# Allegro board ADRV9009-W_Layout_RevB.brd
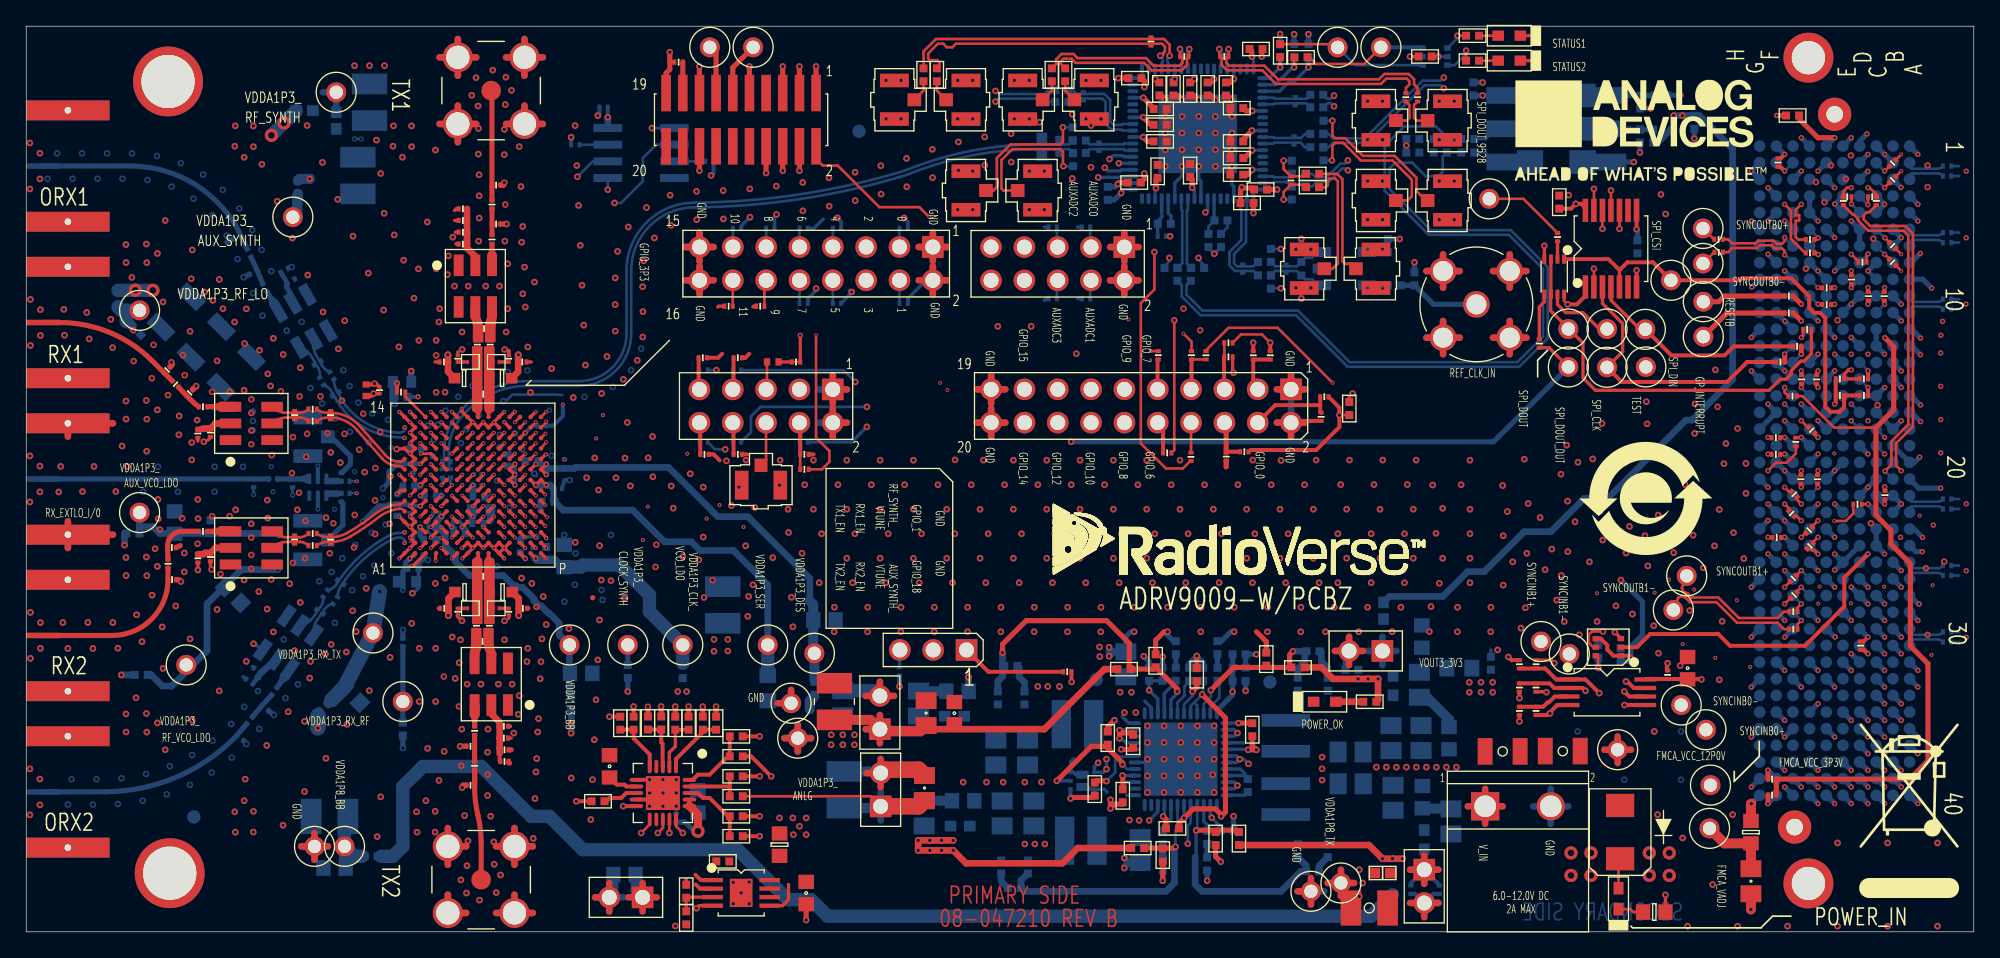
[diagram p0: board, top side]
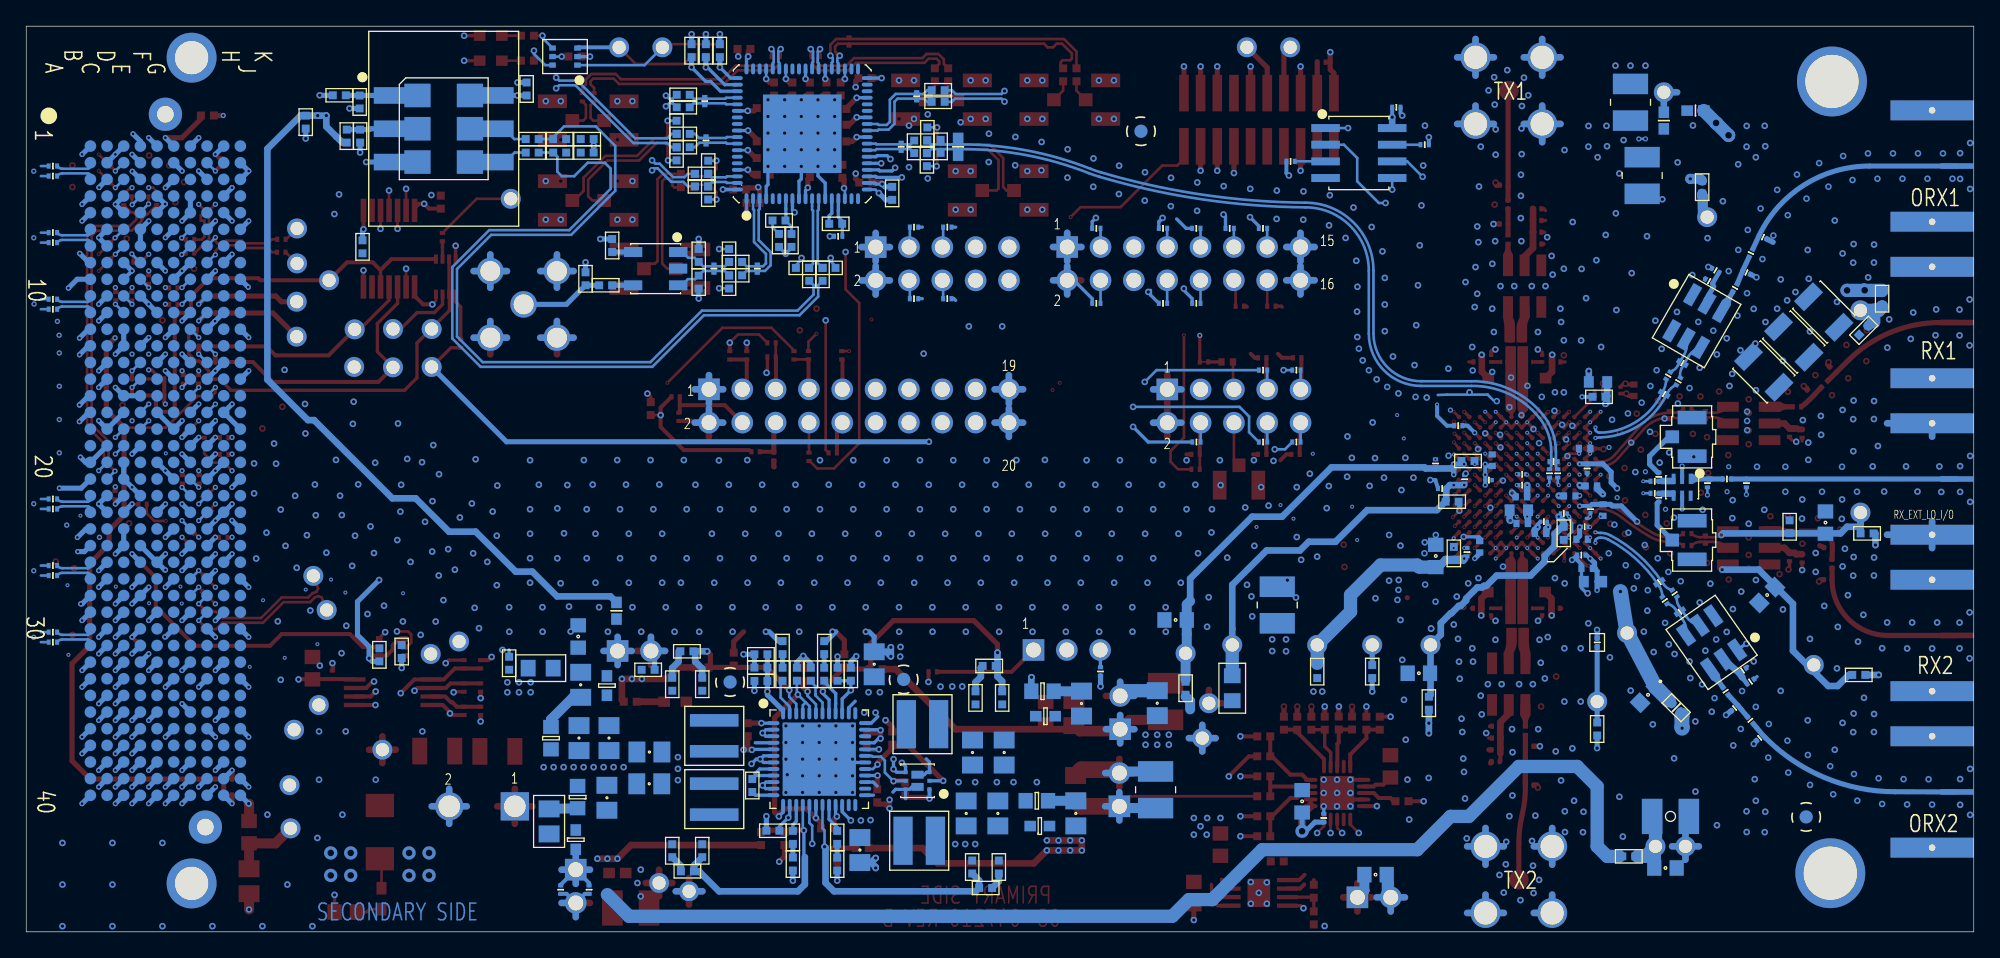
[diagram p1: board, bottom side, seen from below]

Outline 148.44 x 69.09 mm; copper layers: TOP, L2_GND, L3_PWR, L4_GND, L5_SIG, L6_GND, L7_SIG, L8_SIG, L9_GND, L10_SIG, L11_GND, L12_PWR, L13_GND, BOTTOM. Coordinates in mm from the lower left corner of the outline.
Outline path: 0,69.09 0,0 148.44,0 148.44,69.09 0,69.09

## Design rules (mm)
constraint set DEFAULT: min track width 0.203
net group DIFFPAIR0: nets SERDOUT0+ SERDOUT0-
net group DIFFPAIR1: nets SERDOUT1+ SERDOUT1-
net group DIFFPAIR2: nets SERDOUT3+ SERDOUT3-
net group DIFFPAIR3: nets SERDIN3+ SERDIN3-
net group DIFFPAIR4: nets SERDIN0+ SERDIN0-
net group DIFFPAIR5: nets SERDIN2+ SERDIN2-
net group DIFFPAIR13: nets SERDOUT2+ SERDOUT2-
net group DIFFPAIR15: nets SERDIN1+ SERDIN1-
net group DIFFPAIR26: nets GPIO_16 GPIO_17
net group DIFFPAIR27: nets GPIO_13 GPIO_14
net group DIFFPAIR28: nets GPIO_11 GPIO_12
net group DIFFPAIR29: nets GPIO_9 GPIO_10
net group DIFFPAIR30: nets GPIO_8 GPIO_15
net group DIFFPAIR36: nets SYNCOUTB0+ SYNCOUTB0-
net group DIFFPAIR37: nets SYNCINB0+ SYNCINB0-
net group DIFFPAIR38: nets SYNCINB1+ SYNCINB1-
net group DIFFPAIR56: nets SYSREF_IN+ SYSREF_IN-
net group DIFFPAIR59: nets CLK+ CLK-
net group DIFFPAIR63: nets FPGA_SYSREF+ FPGA_SYSREF-
net group DIFFPAIR72: nets VCXO_IN+ VCXO_IN-
net group DIFFPAIR74: nets FPGA_REF_CLK+ FPGA_REF_CLK-
net group DIFFPAIR75: nets DIR_CLK+ DIR_CLK-
net group DIFFPAIR76: nets UNNAMED_2_CAP_I91_N2 UNNAMED_2_CAP_I92_N2
net group DIFFPAIR77: nets UNNAMED_2_CAP_I93_N2 UNNAMED_2_CAP_I94_N2
net group DIFFPAIR78: nets UNNAMED_2_CAP_I95_N2 UNNAMED_2_CAP_I98_N2
net group DIFFPAIR79: nets UNNAMED_2_CAP_I99_N2 UNNAMED_2_CAP_I100_N2
net group DIFFPAIR80: nets UNNAMED_2_CAP_I105_N2 UNNAMED_2_CAP_I106_N2
net group DIFFPAIR81: nets UNNAMED_2_CAP_I101_N2 UNNAMED_2_CAP_I103_N2
net group DIFFPAIR82: nets UNNAMED_2_CAP_I96_N2 UNNAMED_2_CAP_I97_N2
net group DIFFPAIR83: nets UNNAMED_2_CAP_I102_N2 UNNAMED_2_CAP_I104_N2
net group DIFFPAIR84: nets UNNAMED_7_CN400PAK_I55_N15 UNNAMED_7_CN400PAK_I55_N16
net group DIFFPAIR85: nets UNNAMED_7_CN400PAK_I55_N21 UNNAMED_7_CN400PAK_I55_N22
net group DIFFPAIR86: nets UNNAMED_7_CN400PAK_I52_N22 UNNAMED_7_CN400PAK_I52_N23
net group DIFFPAIR87: nets UNNAMED_7_CN400PAK_I55_N24 UNNAMED_7_CN400PAK_I55_N25
net group DIFFPAIR88: nets UNNAMED_4_CAP_I184_N1 UNNAMED_4_RES_I165_N2
net group DIFFPAIR89: nets OUT3 OUT3_N
net group DIFFPAIR91: nets OUT1 OUT1_N
net group DIFFPAIR92: nets UNNAMED_4_CAP_I166_N1 UNNAMED_4_CAP_I177_N1
net group DIFFPAIR93: nets OUT13 OUT13_N
net group DIFFPAIR94: nets OUT12 OUT12_N
net group DIFFPAIR95: nets UNNAMED_7_CN400PAK_I52_N7 UNNAMED_7_CN400PAK_I52_N8
net group DIFFPAIR96: nets UNNAMED_7_CAP_I157_N2 UNNAMED_7_CAP_I158_N2
net group DIFFPAIR97: nets SYNCOUTB1+ SYNCOUTB1-
net group DIFFPAIR98: nets SYSREF_CLK_IN+ SYSREF_CLK_IN-
net group DIFFPAIR99: nets FPGA_SYSREF_OUT+ FPGA_SYSREF_OUT-
net group DIFFPAIR100: nets UNNAMED_4_CNBNC3P_I324_CNTR UNNAMED_4_CNBNC3P_I325_CNTR
net group DIFFPAIR101: nets UNNAMED_4_CAP_I329_N1 UNNAMED_4_CAP_I330_N1
net group DIFFPAIR102: nets REF_CLK_IN+ REF_CLK_IN-
net group DIFFPAIR103: nets ORX1_IN+ ORX1_IN-
net group DIFFPAIR104: nets ORX1_BAL+ ORX1_BAL-
net group DIFFPAIR105: nets RX1_IN+ RX1_IN-
net group DIFFPAIR106: nets RX1_BAL+ RX1_BAL-
net group DIFFPAIR107: nets RF_EXT_LO+ RF_EXT_LO-
net group DIFFPAIR108: nets UNNAMED_10_CAP_I10_N1 UNNAMED_10_CAP_I11_N1
net group DIFFPAIR109: nets RX2_IN+ RX2_IN-
net group DIFFPAIR110: nets RX2_BAL+ RX2_BAL-
net group DIFFPAIR111: nets ORX2_IN+ ORX2_IN-
net group DIFFPAIR112: nets ORX2_BAL+ ORX2_BAL-
net group DIFFPAIR113: nets UNNAMED_4_CNBNC3P_I318_CNTR UNNAMED_4_CNBNC3P_I321_CNTR
net group DIFFPAIR114: nets UNNAMED_4_CAP_I292_N2 UNNAMED_4_CAP_I294_N2
net group DIFFPAIR115: nets OUT5 OUT5_N
net group DIFFPAIR116: nets UNNAMED_4_CAP_I303_N2 UNNAMED_4_CAP_I304_N2
net group DIFFPAIR117: nets OUT7 OUT7_N
net group DIFFPAIR118: nets UNNAMED_4_CNBNC3P_I306_CNTR UNNAMED_4_CNBNC3P_I308_CNTR
net group DIFFPAIR119: nets OUT8 OUT8_N
net group DIFFPAIR120: nets UNNAMED_4_CNBNC3P_I148_CNTR UNNAMED_4_CNBNC3P_I248_CNTR
nets with their own width: min track width 0.254; nets AGND

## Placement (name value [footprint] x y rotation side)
C6  0.1uF  [C0402]  111.64 20.49 270 bottom
C101  1uF  [C0402#2]  37.66 29.38 90 bottom
C102  1uF  [C0402#2]  30.8 33.25 0 bottom
C103  0.1uF  [C0201]  32.34 34.97 270 bottom
C104  0.1uF  [C0201]  31.71 34.97 270 bottom
C105  0.1uF  [C0201]  146.41 58.42 0 bottom
C106  0.1uF  [C0201]  146.41 57.66 0 bottom
C107  0.1uF  [C0201]  146.41 53.34 0 bottom
C108  0.1uF  [C0201]  146.41 52.58 0 bottom
C109  0.1uF  [C0201]  142.25 52.35 315 top
C110  0.1uF  [C0201]  142.25 51.08 315 top
C111  0.1uF  [C0201]  146.41 48.26 0 bottom
C112  0.1uF  [C0201]  146.41 47.5 0 bottom
C113  0.1uF  [C0201]  146.41 33.02 0 bottom
C114  0.1uF  [C0201]  146.41 32.26 0 bottom
C115  0.1uF  [C0201]  146.41 22.86 0 bottom
C116  0.1uF  [C0201]  146.41 22.1 0 bottom
C117  0.1uF  [C0201]  142.25 58.64 45 top
C118  0.1uF  [C0201]  142.25 57.37 45 top
C119  0.1uF  [C0201]  146.41 27.94 0 bottom
C120  0.1uF  [C0201]  146.41 27.18 0 bottom
C121  0.1uF  [C0201]  66.87 53.67 0 bottom
C122  0.1uF  [C0201]  66.87 47.95 0 bottom
C123  0.1uF  [C0201]  61.79 53.67 0 bottom
C124  0.1uF  [C0201]  61.79 47.95 0 bottom
C125  0.1uF  [C0201]  59.25 53.67 0 bottom
C126  0.1uF  [C0201]  59.25 47.95 0 bottom
C127  0.1uF  [C0201]  56.71 53.67 0 bottom
C128  0.1uF  [C0201]  55.95 47.73 180 top
C129  0.1uF  [C0201]  54.17 53.67 0 bottom
C130  0.1uF  [C0201]  53.53 47.73 180 top
C131  0.1uF  [C0201]  80.77 53.76 180 bottom
C132  0.1uF  [C0201]  80.77 48.3 180 bottom
C133  0.1uF  [C0201]  78.23 53.76 180 bottom
C134  0.1uF  [C0201]  78.23 48.3 180 bottom
C135  0.1uF  [C0201]  44.01 62.9 180 bottom
C136  1uF  [C0402#2]  56.9 43.47 0 top
C137  1uF  [C0402#2]  29.66 36.87 180 bottom
C201  TBD0201  [C0201]  10.74 42.87 45 top
C203  TBD0201  [C0201]  12.45 41.12 45 top
C204  TBD0201  [C0201]  20.46 39.42 90 top
C207  TBD0201  [C0201]  23.2 39.42 90 top
C208  TBD0201  [C0201]  11.12 26.87 0 top
C210  TBD0201  [C0201]  11.09 29.31 0 top
C211  TBD0201  [C0201]  20.46 29.92 90 top
C214  TBD0201  [C0201]  23.2 29.92 90 top
C215  TBD0201  [C0201]  16.07 52.99 205 bottom
C217  TBD0201  [C0201]  17.32 50.3 205 bottom
C218  TBD0201  [C0201]  22.21 43.39 210 bottom
C221  TBD0201  [C0201]  23.6 41.04 210 bottom
C222  TBD0201  [C0201]  16.31 14.79 320 bottom
C224  TBD0201  [C0201]  18.22 17.07 320 bottom
C225  TBD0201  [C0201]  22.39 24.42 325 bottom
C228  TBD0201  [C0201]  23.97 26.67 325 bottom
C240  10pF  [C0201]  13.08 38.01 90 top
C241  27PF  [C0201]  14.04 38.08 90 top
C242  82PF  [C0201]  14.04 28.59 90 top
C243  27PF  [C0201]  13.08 28.49 270 top
C244  10pF  [C0201]  19.69 50.46 30 bottom
C245  27PF  [C0201]  20.17 49.64 210 bottom
C246  10pF  [C0201]  17.02 19.09 145 bottom
C247  27PF  [C0201]  17.62 19.93 325 bottom
C248  18PF  [C0201]  13.47 40.05 0 top
C249  18PF  [C0201]  13.47 30.56 0 top
C250  18PF  [C0201]  18.2 49.13 300 bottom
C251  18PF  [C0201]  18.91 18.36 55 bottom
C301  TBD0201  [C0201]  17.33 34.23 270 bottom
C303  TBD0201  [C0201]  20.3 34.23 270 bottom
C304  100pF  [C0201]  24.32 34.37 0 bottom
C305  100pF  [C0201]  24.32 33.45 0 bottom
C307  0.1uF  [C0201]  31.83 43.47 180 top
C308  0.1uF  [C0201]  37.81 43.47 0 top
C312  TBD0201  [C0201]  35.82 54 0 top
C314  TBD0201  [C0201]  35.82 56.97 0 top
C315  0.1uF  [C0201]  37.85 24.68 0 top
C316  0.1uF  [C0201]  31.87 24.68 180 top
C320  TBD0201  [C0201]  33.86 14.15 180 top
C322  TBD0201  [C0201]  33.86 11.18 180 top
C323  TBD0201  [C0201]  32.9 43.73 90 top
C325  TBD0201  [C0201]  36.78 43.73 90 top
C327  TBD0201  [C0201]  36.78 24.42 270 top
C329  TBD0201  [C0201]  32.9 24.42 270 top
C336  18PF  [C0201]  34.18 15.34 270 top
C337  18PF  [C0201]  35.5 52.82 90 top
C338  TBD0201  [C0201]  34.9 46.01 0 top
C339  TBD0201  [C0201]  34.84 41.03 0 top
C341  TBD0201  [C0201]  34.84 27.12 180 top
C342  TBD0201  [C0201]  34.77 22.15 180 top
C344  51PF  [C0201]  33.28 54.27 0 top
C345  75PF  [C0201]  33.28 55.16 0 top
C346  10pF  [C0201]  33.28 52.47 0 top
C347  27PF  [C0201]  33.28 53.37 0 top
C348  10pF  [C0201]  36.4 15.68 180 top
C349  27PF  [C0201]  36.4 14.78 180 top
C350  51PF  [C0201]  36.45 13.88 180 top
C351  75PF  [C0201]  36.45 12.99 180 top
C401  0.1uF  [C0402]  104.28 49.32 180 bottom
C402  0.1uF  [C0402]  94.87 51.6 90 bottom
C403  0.1uF  [C0402]  94.37 51.1 180 bottom
C404  0.1uF  [C0402]  94.87 49.57 270 bottom
C405  0.1uF  [C0402]  94.37 50.09 180 bottom
C406  0.33uF  [C0402]  123.02 63.31 270 bottom
C407  0.1uF  [C0402]  110.3 64.3 270 bottom
C408  0.1uF  [C0402]  105.68 59.45 180 bottom
C409  0.1uF  [C0402]  88.76 50.16 90 bottom
C410  100pF  [C0201]  105.16 63.67 270 top
C411  100pF  [C0201]  106.05 63.67 270 top
C412  0.01uF  [C0402]  78.17 65.38 270 top
C413  0.01uF  [C0402]  79.19 65.38 270 top
C414  180pF  [C0402]  90.11 52.74 90 bottom
C415  1uF  [C0402]  91.06 52.74 90 bottom
C416  1000pF  [C0402]  86.74 54.01 0 bottom
C417  0.47uF  [C0201]  86.55 53.06 0 bottom
C418  0.1uF  [C0402]  86.43 60.3 0 top
C419  0.1uF  [C0402]  96.46 58.33 270 bottom
C420  0.1uF  [C0402]  96.46 56.36 90 bottom
C421  0.1uF  [C0402]  121.52 21.13 270 bottom
C422  0.1uF  [C0402]  119.82 21.38 270 bottom
C423  0.1uF  [C0402]  122.81 52.26 90 bottom
C424  0.1uF  [C0402]  116.84 55.67 270 top
C425  0.1uF  [C0402]  100.84 39.92 90 top
C426  1uF  [C0402]  86.24 58.02 90 top
C427  0.1uF  [C0402]  88.71 58.08 270 top
C428  0.1uF  [C0402]  93.04 55.6 0 top
C429  0.1uF  [C0402]  94.08 56.63 0 top
C430  0.1uF  [C0402]  92.27 57.76 0 top
C431  0.1uF  [C0402]  92.27 59.03 0 top
C432  0.1uF  [C0402]  92.27 60.3 0 top
C433  0.1uF  [C0402]  92.27 62.84 0 top
C434  0.1uF  [C0402]  93.73 67.35 180 top
C435  0.1uF  [C0402]  91.44 64.3 90 top
C436  0.1uF  [C0402]  90.05 64.3 90 top
C437  0.1uF  [C0402]  88.71 64.3 90 top
C438  0.1uF  [C0402]  87.44 64.3 90 top
C439  0.1uF  [C0402]  86.36 64.3 90 top
C440  0.1uF  [C0402]  106.62 66.78 0 top
C441  0.1uF  [C0402]  84.45 57.16 180 top
C442  0.1uF  [C0402]  86.43 61.57 180 top
C443  0.1uF  [C0402]  86.43 62.78 180 top
C444  0.1uF  [C0402]  84.51 65.13 180 top
C445  TBD0402  [C0402]  78.74 59.92 270 bottom
C601  10uF  [C0603]  70.74 16.68 90 top
C602  220UF  [C1210-2]  61.6 17.57 90 top
C603  10uF  [C0603]  42.29 19.72 0 bottom
C604  0.1uF  [C0201]  31.24 31.92 180 bottom
C605  1uF  [C0402]  31.25 30.4 270 bottom
C606  220UF  [C1210-2]  25.28 57.7 270 bottom
C607  220UF  [C1210-2]  26.16 63.29 90 bottom
C608  0.1uF  [C0201]  34.42 34.08 0 bottom
C609  1uF  [C0402#2]  34.48 33.19 0 bottom
C610  10uF  [C0603]  41 28.67 90 bottom
C611  0.1uF  [C0201]  38.63 28.96 90 bottom
C612  1uF  [C0402]  39.63 28.87 90 bottom
C613  10uF  [C0603#2]  29.02 26.71 0 bottom
C614  1uF  [C0402#2]  29.47 27.73 0 bottom
C615  0.1uF  [C0201]  29.91 28.74 0 bottom
C616  10uF  [C0603#2]  34.67 32.17 0 bottom
C617  1uF  [C0402#2]  34.42 31.15 0 bottom
C618  10uF  [C0603]  24.83 18.08 315 bottom
C619  0.1uF  [C0201]  29.66 30.9 180 bottom
C620  1uF  [C0402#2]  29.85 29.95 180 bottom
C621  10uF  [C0603]  11.31 31.22 90 bottom
C622  0.1uF  [C0201]  29.47 35.35 270 bottom
C623  1uF  [C0402]  14.04 30.9 90 bottom
C624  220UF  [C1210-2#2]  13.72 45 45 bottom
C625  220UF  [C1210-2#2]  11.43 47.28 45 bottom
C626  220UF  [C1210-2#2]  16 42.71 45 bottom
C627  1uF  [C0402#2]  29.15 34.01 180 bottom
C628  10uF  [C0603]  15.75 25.69 315 bottom
C629  0.1uF  [C0201]  29.21 32.23 270 bottom
C630  1uF  [C0402#2]  28.26 32.17 270 bottom
C631  10uF  [C0603#2]  28.64 41.95 0 bottom
C632  0.1uF  [C0201]  34.42 34.9 0 bottom
C633  1uF  [C0402]  28.56 40.81 0 bottom
C634  0.1uF  [C0201]  40.52 33.82 0 bottom
C635  1uF  [C0402]  39.76 32.81 180 bottom
C636  0.1uF  [C0201]  38.8 34.52 90 bottom
C637  10uF  [C0603]  60.84 23.79 0 bottom
C638  0.1uF  [C0201]  41.02 35.73 90 bottom
C639  1uF  [C0402]  38.55 35.92 180 bottom
C640  220UF  [C1210-2]  62.36 10.83 90 bottom
C641  220UF  [C1210-2]  53.09 24.93 90 bottom
C642  0.1uF  [C0201]  36.96 34.46 180 bottom
C643  1uF  [C0402#2]  36.71 35.98 90 bottom
C701  0.1uF  [C0201]  49.54 8.68 270 bottom
C702  10uF  [C0603]  51.19 9.95 90 bottom
C703  10uF  [C0603]  126.63 20.11 90 top
C704  0.1uF  [C0201]  125.1 19.6 90 top
C705  10uF  [C0603]  44.46 12.62 90 top
C706  1uF  [C0402]  43.58 9.96 180 top
C801  0.01uF  [C0201]  140.7 56.06 180 top
C802  0.01uF  [C0201]  138.8 56.06 0 top
C803  0.01uF  [C0201]  141.01 55.76 270 top
C804  0.01uF  [C0201]  138.5 55.76 270 top
C901  10uF  [C0805H60]  83.81 20.41 90 bottom
C902  1uF  [C0402]  89.7 19.65 270 bottom
C903  1uF  [C0402]  89.22 19.62 270 top
C904  0.0027uF  [C0402]  87.62 21.68 270 bottom
C905  10uF  [C0805H60]  84.9 6.24 270 bottom
C906  0.0027uF  [C0402]  86.63 5.17 90 bottom
C907  10uF  [C0805H60]  100.94 13.72 0 bottom
C908  0.0033uF  [C0402]  90.79 21.68 270 bottom
C909  10uF  [C0805H60]  100.95 11.29 0 bottom
C910  0.0033uF  [C0402]  90 5.17 90 bottom
C911  TBD0402  [C0402]  86.6 19.65 270 bottom
C912  TBD0402  [C0402]  92.44 21.17 180 bottom
C913  0.1uF  [C0402]  84.37 14.54 90 top
C914  0.01uF  [C0402]  76.09 17.84 270 bottom
C915  0.1uF  [C0402]  83.58 10.38 90 top
C916  0.01uF  [C0402]  74.31 4.94 90 bottom
C917  0.1uF  [C0402]  93.45 15.42 270 top
C918  0.01uF  [C0402]  99.2 18.88 270 bottom
C919  0.1uF  [C0402]  93.1 11.16 90 bottom
C920  0.01uF  [C0402]  99.2 6.18 90 bottom
C921  47uF  [C0805H60]  76.31 13.68 270 bottom
C922  47uF  [C0805H60]  73.9 13.68 270 bottom
C924  47uF  [C0805H60]  68.01 17.41 90 bottom
C925  47uF  [C0805H60]  76.8 9.03 90 bottom
C926  47uF  [C0805H60]  74.38 9.03 90 bottom
C927  47uF  [C0805H60]  68.44 9.03 90 bottom
C928  47uF  [C0805H60]  104.02 14.78 270 bottom
C929  47uF  [C0805H60]  106.18 18.84 270 bottom
C930  47uF  [C0805H60]  104.18 10.22 90 bottom
C931  22uF  [C0805H53]  108.59 8.42 90 bottom
C932  47uF  [C0805H60]  131.45 3.86 270 top
C933  4.7uF  [C0603]  59.45 2.96 90 top
C934  4.7uF  [C0603]  45.6 4.36 0 bottom
C935  0.01uF  [C0402]  53.09 5.37 180 top
C936  10uF  [C0603]  106.37 22.53 90 bottom
C937  0.01uF  [C0402]  101.04 19.99 0 bottom
C938  0.1uF  [C0402]  127.14 61.77 90 bottom
C939  47uF  [C0805H60]  106.31 14.78 270 bottom
C940  0.1uF  [C0201]  105.54 3.21 90 bottom
C941  0.01uF  [C0201]  107.7 3.21 90 bottom
C942  100uF  [C1210]  23.12 8.8 180 bottom
C943  10uF  [C0603]  23.5 4.87 180 bottom
C944  0.1uF  [C0201]  32.77 31.28 0 bottom
C945  1uF  [C0402#2]  33.02 30.39 0 bottom
C946  100uF  [C1210]  102.36 1.82 0 top
C947  0.1uF  [C0201]  26.93 41.31 90 top
C948  1uF  [C0402#2]  25.91 41.31 90 top
C949  47uF  [C0805H60]  62.23 17.44 90 bottom
C950  47uF  [C0805H60]  68.59 16.68 90 top
C951  47uF  [C0805H60]  68.46 10.97 90 top
CR901  S2A-LT  [DO214AA3]  121.48 7.6 90 top
DS401  LNJ326W83RA  [LED0603_A]  113.03 66.46 180 top
DS402  LNJ326W83RA  [LED0603_A]  113.03 68.37 180 top
DS901  LNJ926W8CRA  [LED0603]  121.36 2.52 90 top
DS902  LNJ326W83RA  [LED0603_A]  98.97 17.55 0 top
E602  1.8K OHM AT 100MEGHZ  [L0402]  21.21 62.65 0 bottom
E611  42OHM AT 100MEGHZ  [L0805]  56.52 18.58 90 bottom
E613  1.8KOHM AT 100MEGHZ  [L0402]  23.62 61.89 270 bottom
E901  120OHM  [L0603]  70.75 16.45 180 bottom
E902  470OHM  [L0603]  71.18 8.06 180 bottom
E903  470OHM  [L0603]  104.18 18.78 90 bottom
E904  470OHM  [L0603]  106.56 7.02 270 bottom
E905  42OHM AT 100MEGHZ  [L0805]  109.23 20.11 0 bottom
E906  30OHM  [L0402]  103.45 24.49 90 bottom
E907  30OHM  [L0402]  103.38 4.48 180 top
F901  2A  [F1206]  117.11 13.78 180 top
F902  2A  [F1206]  112.53 13.76 0 top
J101  U.FL-R-SMT-1(01)  [CNHIROSE-U_FL-R-SMT-1]  56 34.07 180 top
J201  132255-11  [CNAMPHENOL132255-11]  0.76 46.48 180 top
J202  132255-11  [CNAMPHENOL132255-11]  0.76 22.61 180 top
J203  132255-11  [CNAMPHENOL132255-11]  0.76 58.42 180 bottom
J204  132255-11  [CNAMPHENOL132255-11]  0.76 10.67 180 bottom
J301  132255-11  [CNAMPHENOL132255-11]  0.76 34.54 180 bottom
J303  132134-15  [CNSMSMASQ276H379]  35.44 64.17 90 top
J304  132134-15  [CNSMSMASQ276H379]  34.67 3.98 90 top
J305  U.FL-R-SMT-1(01)  [CNHIROSE-U_FL-R-SMT-1]  21.47 37.76 270 bottom
J306  U.FL-R-SMT-1(01)  [CNHIROSE-U_FL-R-SMT-1]  21.47 29.88 270 bottom
J401  142-0701-201  [CNJOHNSON142-0701-201]  110.53 47.87 0 top
J402  U.FL-R-SMT-1(01)  [CNHIROSE-U_FL-R-SMT-1]  102.87 55.79 90 top
J403  U.FL-R-SMT-1(01)  [CNHIROSE-U_FL-R-SMT-1]  108.33 55.79 270 top
J404  U.FL-R-SMT-1(01)  [CNHIROSE-U_FL-R-SMT-1]  102.87 61.89 90 top
J405  U.FL-R-SMT-1(01)  [CNHIROSE-U_FL-R-SMT-1]  108.33 61.89 270 top
J406  U.FL-R-SMT-1(01)  [CNHIROSE-U_FL-R-SMT-1]  75.95 63.48 90 top
J407  U.FL-R-SMT-1(01)  [CNHIROSE-U_FL-R-SMT-1]  81.41 63.48 270 top
J408  U.FL-R-SMT-1(01)  [CNHIROSE-U_FL-R-SMT-1]  71.63 63.48 270 top
J409  U.FL-R-SMT-1(01)  [CNHIROSE-U_FL-R-SMT-1]  66.17 63.48 90 top
J410  U.FL-R-SMT-1(01)  [CNHIROSE-U_FL-R-SMT-1]  71.63 56.55 90 top
J411  U.FL-R-SMT-1(01)  [CNHIROSE-U_FL-R-SMT-1]  77.09 56.55 270 top
J412  U.FL-R-SMT-1(01)  [CNHIROSE-U_FL-R-SMT-1]  102.87 50.59 270 top
J413  U.FL-R-SMT-1(01)  [CNHIROSE-U_FL-R-SMT-1]  97.41 50.59 90 top
L307  43NH  [L0603]  33.37 42.24 180 top
L308  43NH  [L0603]  36.27 42.24 180 top
L315  43NH  [L0603]  36.3 25.92 0 top
L316  43NH  [L0603]  33.41 25.92 0 top
L323  TBD0201  [L0201]  33.85 43.47 180 top
L325  TBD0201  [L0201]  35.82 43.47 0 top
L327  TBD0201  [L0201]  35.82 24.68 0 top
L329  TBD0201  [L0201]  33.85 24.68 180 top
L401  TBD0402  [L0402]  77.41 59.89 90 bottom
L612  TBD0201  [L0201]  28.7 22.07 90 bottom
L900  2.2uH  [LSMSQ157H83]  80.12 15.84 180 bottom
L901  2.2uH  [LSMSQ157H83]  80.38 6.95 180 bottom
L902  6.8uH  [LSMSQ157H122]  96 14.95 90 bottom
L903  6.8uH  [LSMSQ157H122]  96 10.12 270 bottom
NOREF  -  []  -140.27 -283.34 0 top
NOREF#2  -  []  123.07 61.13 0 top
NOREF#3  -  [unnamed#2]  135.84 66.69 0 top
NOREF#4  -  [unnamed#2]  135.84 3.69 0 top
NOREF#5  -  []  -96.05 -19.57 0 top
NOREF#6  -  []  123.45 33.06 0 top
NOREF#7  -  []  250.38 218.8 0 top
NOREF#8  -  []  65.26 90.52 0 top
NOREF#9  -  []  -140.27 -283.34 0 top
NOREF#10  -  [unnamed#2]  10.93 4.47 0 top
NOREF#11  -  [unnamed#2]  10.81 64.87 0 top
NOREF#12  -  []  0 69.09 0 top
NOREF#13  -  []  280.93 -40.72 0 top
NOREF#14  -  []  3.55 -12.7 90 top
NOREF#15  -  []  154.73 137.11 0 top
NOREF#16  -  []  100.91 114.35 0 top
NOREF#17  -  []  -140.27 -283.34 0 top
NOREF#18  -  []  148.44 0 90 top
NOREF#19  -  []  152.78 19.47 0 top
NOREF#20  -  [unnamed#2]  12.78 8.76 0 bottom
NOREF#21  -  [unnamed#2]  63.47 61.07 90 bottom
NOREF#22  -  [unnamed#2]  81.56 19.25 0 bottom
NOREF#23  -  [unnamed#2]  94.79 19.06 0 bottom
P101  TSW-110-08-G-D  [CNBERG2X10H330LD36]  96.4 41.39 180 top
P102  TSW-108-08-G-D  [CNSAMTECTSW-108-08-G-D-ST]  69.1 52.24 180 top
P103  TSW-105-08-G-D  [CNSAMTEC2X5H338LD36]  83.7 52.24 180 top
P104  TSW-105-08-G-D  [CNSAMTEC2X5H338LD36]  61.47 41.38 180 top
P701  FTSH-110-01-L-DV-K  [CNHDR2X10H251]  54.49 61.95 180 top
P801  ASP-134488-01  [CNSAMTECASP-134488-01]  143.55 59.94 270 bottom
P901  Z5.530.3225.0  [CNWIELAND3225]  111.2 9.57 0 top
P902  TSW-103-08-G-S  [CNBERG1X3H205LD36]  71.67 21.5 180 top
P903  TSW-102-08-G-S  [CNSAMTEC1X2H330LD36]  65.06 16.73 90 top
P904  TSW-102-08-G-S  [CNSAMTEC1X2H330LD36]  65.12 10.84 90 top
P905  TSW-102-08-G-S  [CNSAMTEC1X2H330LD36]  102.1 21.42 180 top
P906  TSW-102-08-G-S  [CNSAMTEC1X2H330LD36]  106.56 3.47 270 top
P907  TSW-102-08-G-S  [CNSAMTEC1X2H330LD36]  45.71 2.63 180 top
Q901  SIA906EDJ-T1-GE3  [POWERPAKSC70-6]  80.51 11.52 90 bottom
R101  14.3K  [R0201]  28.57 41.18 180 top
R102  10K  [R0201]  91.63 44.93 180 top
R103  10K  [R0201]  91.63 43.85 0 top
R104  10K  [R0201]  92.85 36.62 180 top
R105  10K  [R0201]  91.46 36.25 270 top
R106  10K  [R0201]  94.81 43.98 270 top
R107  10K  [R0201]  93.52 43.98 90 top
R108  10K  [R0201]  98.94 40.81 180 top
R109  10K  [R0201]  98.69 39.29 270 top
R110  10K  [R0201]  39.29 38.61 0 bottom
R111  10K  [R0201]  133.07 11.65 0 top
R112  1K  [R0201]  133.07 10.43 180 top
R113  10K  [R0201]  59.31 36.43 0 top
R114  10K  [R0201]  51.69 36.43 0 top
R115  10K  [R0201]  51.56 43.79 0 top
R116  10K  [R0201]  54.23 36.43 0 top
R117  10K  [R0201]  54.23 43.79 0 top
R118  10K  [R0201]  58.68 43.47 0 top
R119  10K  [R0201]  41.85 60.05 0 bottom
R120  10K  [R0201]  52.07 58.78 180 bottom
R121  100  [R0201]  32.03 35.86 180 bottom
R202  0  [R0201]  11.38 41.78 315 top
R205  0  [R0201]  21.83 38.96 0 top
R206  0  [R0201]  21.83 39.87 0 top
R209  0  [R0201]  10.8 28.08 90 top
R212  0  [R0201]  21.83 29.47 0 top
R213  0  [R0201]  21.83 30.38 0 top
R216  0  [R0201]  16.98 51.78 295 bottom
R219  0  [R0201]  23.29 42.43 300 bottom
R220  0  [R0201]  22.51 42 300 bottom
R223  0  [R0201]  17.03 16.14 50 bottom
R226  0  [R0201]  22.8 25.81 55 bottom
R227  0  [R0201]  23.55 25.28 55 bottom
R302  0  [R0201]  18.82 34.54 0 bottom
R304  0  [R0201]  24.01 34.71 270 bottom
R305  0  [R0201]  24.01 33.12 90 bottom
R307  0  [R0201]  34.38 44.8 90 top
R308  0  [R0201]  35.36 44.8 90 top
R309  0  [R0201]  35.5 55.48 90 top
R310  0  [R0201]  35.29 23.35 270 top
R311  0  [R0201]  34.32 23.35 270 top
R312  0  [R0201]  34.18 12.67 270 top
R401  49.9  [R0402]  105.81 49.82 270 bottom
R402  0  [R0402]  103.78 52.36 270 bottom
R403  24.9  [R0402]  97.18 51.6 90 bottom
R404  24.9  [R0402]  97.18 49.57 90 bottom
R405  100  [R0201]  96.02 50.59 270 bottom
R406  100  [R0201]  92.72 50.59 270 bottom
R407  0  [R0402]  124.57 63.82 180 bottom
R408  0  [R0402]  124.01 60.71 90 bottom
R409  0  [R0402]  122.99 60.71 90 bottom
R410  0  [R0402]  109.87 59.45 180 bottom
R411  0  [R0402]  87.74 50.16 90 bottom
R412  49.9  [R0402]  107.78 59.45 0 bottom
R413  0  [R0402]  107.78 60.48 180 bottom
R414  0  [R0402]  105.68 60.48 180 bottom
R415  0  [R0402]  87.25 50.65 180 bottom
R416  0  [R0402]  89.28 50.65 0 bottom
R417  0  [R0402]  109.87 60.48 180 bottom
R418  100  [R0201]  96.63 60.37 270 bottom
R419  0  [R0402]  98.36 59.86 0 bottom
R420  0  [R0402]  98.36 60.87 0 bottom
R421  0  [R0402]  98.87 59.35 90 bottom
R422  0  [R0402]  98.87 61.38 270 bottom
R423  100  [R0201]  96.72 63.38 90 bottom
R424  0  [R0402]  98.36 63.86 0 bottom
R425  0  [R0402]  98.36 62.9 0 bottom
R426  100  [R0201]  91.32 66.78 0 top
R427  100  [R0201]  88.27 66.78 0 top
R428  100  [R0201]  85.73 67.92 90 top
R429  0  [R0402]  69.41 65.38 270 top
R430  0  [R0402]  68.39 65.38 270 top
R431  100  [R0201]  80.57 63.74 270 bottom
R432  0  [R0402]  78.93 63.32 180 bottom
R433  0  [R0402]  78.93 64.21 180 bottom
R434  100  [R0201]  81.75 59.89 90 bottom
R435  0  [R0402]  80.27 60.36 180 bottom
R436  0  [R0402]  80.27 59.41 180 bottom
R437  0  [R0402]  79.76 60.87 90 bottom
R438  0  [R0402]  79.79 58.9 270 bottom
R439  10.2K  [R0402]  91.06 54.27 180 bottom
R440  10K  [R0402]  82.44 56.34 270 bottom
R441  10K  [R0402]  97.73 67.22 270 bottom
R442  10K  [R0402]  95.57 67.22 90 bottom
R443  10K  [R0402]  96.64 67.22 90 bottom
R444  0  [R0402]  95.57 67.22 90 top
R445  0  [R0402]  97.16 66.71 0 top
R446  200  [R0402]  110.24 66.46 0 top
R447  200  [R0402]  110.24 68.37 0 top
R448  0  [R0402]  98.05 57.82 180 top
R449  0  [R0402]  98.05 56.81 180 top
R450  100  [R0201]  96.4 57.32 270 top
R451  0  [R0402]  96.97 57.82 180 bottom
R452  0  [R0402]  96.97 56.87 180 bottom
R453  0  [R0201]  116.72 53 90 top
R454  0  [R0201]  115.33 44.88 270 top
R601  0  [R0402]  41.53 17.44 90 bottom
R603  0  [R0402]  50.04 19.85 90 bottom
R604  0  [R0402]  28.7 15.47 90 bottom
R605  0  [R0402]  45.85 19.85 90 bottom
R606  0  [R0402]  22.68 17.1 45 bottom
R607  0  [R0402]  8.13 30.39 0 bottom
R608  0  [R0402]  6.99 48.3 270 bottom
R609  0  [R0402]  8.77 19.6 0 bottom
R610  0  [R0402]  20.7 56.81 270 bottom
R611  0  [R0402]  60.07 18.58 90 bottom
R612  0  [R0201]  28.7 22.07 90 bottom
R613  0.1  [R0402]  8.38 45.89 315 bottom
R701  47K  [R0201]  49.72 66.35 0 top
R702  0  [R0201]  86.28 43.99 270 top
R704  0  [R0201]  59.31 35.28 180 top
R705  0  [R0201]  88.82 43.99 270 top
R706  0  [R0201]  86.97 36.53 180 top
R707  0  [R0201]  88.78 36.23 90 top
R708  20K  [R0201]  113.8 20.41 90 top
R709  20K  [R0201]  113.8 18.63 270 top
R710  20K  [R0201]  113.8 16.85 270 top
R711  20K  [R0201]  115.07 20.41 270 top
R712  20K  [R0201]  115.07 18.63 90 top
R713  20K  [R0201]  115.07 16.85 90 top
R714  56K  [R0402]  54.12 7.29 0 top
R715  10K  [R0402]  54.12 8.81 0 top
R716  10K  [R0402]  54.12 10.34 180 top
R717  10K  [R0402]  54.12 11.86 180 top
R718  10K  [R0402]  54.12 13.39 180 top
R719  10K  [R0402]  54.12 14.91 180 top
R720  10K  [R0402]  51.56 15.91 270 top
R721  10K  [R0402]  52.58 15.91 270 top
R722  10K  [R0402]  49.47 15.91 270 top
R723  10K  [R0402]  50.48 15.91 270 top
R724  10K  [R0402]  47.39 15.93 270 top
R725  10K  [R0402]  48.4 15.93 270 top
R726  10K  [R0402]  45.28 15.91 270 top
R727  10K  [R0402]  46.29 15.91 270 top
R801  0  [R0201]  133.52 58.69 270 top
R802  0  [R0201]  128.99 52.83 0 top
R803  0  [R0201]  129 51.84 0 top
R804  0  [R0201]  134.34 48.5 0 top
R805  0  [R0201]  134.34 47.21 0 top
R806  0  [R0201]  133.71 43.47 0 top
R807  0  [R0201]  134.98 44.67 0 top
R808  0  [R0201]  133.35 37.7 0 top
R809  0  [R0201]  133.35 36.43 0 top
R810  0  [R0201]  134.75 33.38 315 top
R811  0  [R0201]  134.56 31.92 315 top
R812  0  [R0201]  133.42 30.08 0 top
R813  0  [R0201]  89.92 43.98 90 top
R814  0  [R0201]  134.69 24.42 0 top
R815  0  [R0201]  134.69 23.09 0 top
R816  0  [R0201]  140.4 48.49 270 top
R817  0  [R0201]  141.61 48.49 270 top
R818  0  [R0201]  135.96 52.81 0 top
R819  0  [R0201]  135.96 51.79 0 top
R820  0  [R0201]  137.23 49.13 180 top
R821  0  [R0201]  137.23 47.86 180 top
R822  0  [R0201]  136.08 38.27 315 top
R823  0  [R0201]  134.88 37.38 90 top
R824  0  [R0201]  135.26 34.52 270 top
R825  0  [R0201]  136.53 34.52 270 top
R826  0  [R0201]  135.89 30.65 45 top
R827  0  [R0201]  135.96 29.44 225 top
R828  0  [R0201]  134.69 26.96 45 top
R829  0  [R0201]  134.75 25.69 45 top
R830  0  [R0201]  136.46 42.14 270 top
R831  0  [R0201]  135.32 42.14 270 top
R832  10K  [R0201]  138.24 42.19 0 top
R833  10K  [R0201]  138.24 40.92 0 top
R834  0  [R0201]  139.96 51.09 0 top
R835  0  [R0201]  139.13 49.76 270 top
R836  0  [R0201]  134.62 40.87 180 top
R837  0  [R0201]  59.25 37.37 0 bottom
R838  0  [R0201]  51.63 42.85 0 bottom
R839  0  [R0201]  54.17 42.85 0 bottom
R840  0  [R0201]  139.81 21.83 90 top
R841  0  [R0201]  51.63 37.37 0 bottom
R842  0  [R0201]  54.17 37.37 0 bottom
R843  0  [R0201]  141.67 33.31 270 top
R844  0  [R0201]  139.58 32.62 0 top
R845  0  [R0201]  135.75 45.94 180 top
R846  0  [R0201]  140.06 42.19 0 top
R847  0  [R0201]  140.06 40.92 0 top
R848  1K  [R0402]  134.63 62.28 0 top
R901  2K  [R0603]  124.09 1.51 180 top
R902  200  [R0201]  79.35 19.83 180 top
R903  100K  [R0402]  87.36 7.89 0 top
R904  10K  [R0402]  87.62 19.65 270 bottom
R905  43.2K  [R0402]  85.59 19.65 270 bottom
R906  100K  [R0402]  91.53 7.71 0 bottom
R907  10K  [R0402]  86.63 7.2 90 bottom
R908  20K  [R0402]  90.79 19.65 270 bottom
R909  56K  [R0402]  92.44 19.14 180 bottom
R910  14K  [R0402]  92.44 20.15 0 bottom
R911  20K  [R0402]  90 7.2 90 bottom
R912  0  [R0201]  66.56 19.86 270 bottom
R913  22.1K  [R0402]  88.63 19.65 90 bottom
R914  10K  [R0402]  86.08 20.67 90 top
R915  0  [R0402]  75.04 20.28 0 bottom
R916  6.34K  [R0402]  83.67 20.04 180 top
R917  10.7K  [R0402]  74.05 17.84 270 bottom
R918  47K  [R0402]  81.45 10.88 90 top
R919  47K  [R0402]  82.43 14.78 270 top
R920  10K  [R0402]  86.63 5.85 90 top
R921  0  [R0402]  75.31 3.34 180 bottom
R922  10K  [R0402]  76.34 4.94 90 bottom
R923  6.34K  [R0402]  84.71 6.39 180 top
R924  10K  [R0402]  94.51 20.8 270 top
R925  0  [R0402]  98.08 21.4 0 bottom
R926  37.4K  [R0402]  96.91 18.88 270 bottom
R927  31.6K  [R0402]  96.93 20.17 0 top
R928  10K  [R0402]  90.65 7.11 90 top
R929  0  [R0402]  98.05 4.61 0 bottom
R930  27.4K  [R0402]  96.91 6.18 90 bottom
R931  12.7K  [R0402]  92.43 7.11 270 top
R932  0.1  [R0603]  70.98 18.35 0 bottom
R933  0.1  [R0603]  71.41 9.99 0 bottom
R934  0.1  [R0603]  108.45 14.77 270 bottom
R935  200  [R0402]  102.4 17.55 180 top
R936  0  [R0603]  57.41 6.65 270 top
R937  0.47  [R0603]  106.41 10.27 90 bottom
R938  0  [R0603]  131.45 7.6 90 top
R939  20K  [R0402]  50.3 3.09 90 top
R940  4.99K  [R0402]  50.3 1.06 90 top
R941  0  [R0402]  103.38 4.48 180 top
R942  0  [R0402]  26.29 5.75 180 bottom
T201  TCM1-83X+  [TSML150W160H160]  17.15 38.78 90 top
T202  TCM1-83X+  [TSML150W160H160]  17.15 29.29 90 top
T205  TCM1-83X+  [TSML150W160H160]  21.12 46.59 210 bottom
T207  TCM1-83X+  [TSML150W160H160]  19.98 22.08 325 bottom
T301  HHM1595A1  [T0805_A]  22.23 33.91 0 bottom
T302  TCM1-83X+  [TSML150W160H160]  34.23 49.26 0 top
T303  TCM1-83X+  [TSML150W160H160]  35.45 18.89 180 top
T401  MABA-007159-000000  [ETC1]  100.47 50.59 270 bottom
TP400  WHT  [CNKEY5001TP]  111.51 55.92 0 top
TP401  WHT  [CNKEY5001TP]  117.54 43.09 0 top
TP402  WHT  [CNKEY5001TP]  103.25 67.48 180 top
TP403  WHT  [CNKEY5001TP]  99.95 67.48 180 top
TP601  WHT  [CNKEY5001TP]  58.8 14.77 0 top
TP602  WHT  [CNKEY5001TP]  58.3 17.44 0 top
TP603  WHT  [CNKEY5001TP]  41.4 21.88 0 top
TP604  WHT  [CNKEY5001TP]  23.62 64.05 0 top
TP605  WHT  [CNKEY5001TP]  50.04 21.88 0 top
TP606  WHT  [CNKEY5001TP]  28.7 17.57 0 top
TP607  WHT  [CNKEY5001TP]  45.85 21.88 0 top
TP608  WHT  [CNKEY5001TP]  26.42 22.8 0 top
TP609  WHT  [CNKEY5001TP]  8.64 31.98 0 top
TP610  WHT  [CNKEY5001TP]  8.64 47.41 0 top
TP611  WHT  [CNKEY5001TP]  12.19 20.36 0 top
TP612  WHT  [CNKEY5001TP]  20.32 54.52 0 top
TP613  WHT  [CNKEY5001TP]  56.52 21.88 0 top
TP614  WHT  [CNKEY5001TP]  60.07 21.25 0 top
TP701  WHT  [CNKEY5001TP]  52.1 67.48 180 top
TP702  WHT  [CNKEY5001TP]  55.4 67.48 180 top
TP801  WHT  [CNKEY5001TP]  127.8 53.66 0 top
TP802  WHT  [CNKEY5001TP]  127.8 50.99 0 top
TP803  WHT  [CNKEY5001TP]  127.83 48.07 0 top
TP804  WHT  [CNKEY5001TP]  127.83 45.4 0 top
TP805  WHT  [CNKEY5001TP]  120.48 43.07 0 top
TP806  WHT  [CNKEY5001TP]  123.41 45.96 0 top
TP807  WHT  [CNKEY5001TP]  126.56 27.15 0 top
TP808  WHT  [CNKEY5001TP]  125.54 24.55 0 top
TP809  WHT  [CNKEY5001TP]  128.03 15.41 45 top
TP810  WHT  [CNKEY5001TP]  126.14 17.3 45 top
TP811  WHT  [CNKEY5001TP]  117.54 45.99 0 top
TP812  WHT  [CNKEY5001TP]  115.45 22.14 0 top
TP813  WHT  [CNKEY5001TP]  117.61 21.19 0 top
TP814  WHT  [CNKEY5001TP]  128.3 7.89 0 top
TP815  WHT  [CNKEY5001TP]  125.36 49.7 0 top
TP816  WHT  [CNKEY5001TP]  120.48 45.99 0 top
TP817  WHT  [CNKEY5001TP]  123.45 43.09 0 top
TP818  WHT  [CNKEY5001TP]  128.37 11.19 0 top
TP819  WHT  [CNKEY5001TP]  121.29 13.89 0 top
TP901  WHT  [CNKEY5001TP]  100.21 3.72 0 top
TP902  WHT  [CNKEY5001TP]  97.92 3.09 0 top
TP903  WHT  [CNKEY5001TP]  24.26 6.52 0 top
TP904  WHT  [CNKEY5001TP]  21.97 6.52 0 top
U101  ADRV9009  [BGA196]  34.04 34.08 0 top
U102  S25FL208K0RMFI041  [SO8]  46.87 59.41 270 bottom
U401  AD9528BCPZ  [QFN72_10X10_PAD5_3X5_3]  89.29 60.88 180 bottom
U402  NC7WV125K8X  [US8]  116.46 49.98 180 top
U403  ADG3304SRU-EP  [TSSOP14]  120.79 52.12 0 top
U404  ADG3301BKSZ  [SC70-6]  120.58 21.71 90 top
U405  NC7WZ16P6X  [SC70]  107.37 66.77 90 bottom
U702  M24C02-FDW6TP  [TSSOP8]  120.48 18.28 270 top
U703  AD7291BCPZ  [QFN20_4X4_PAD2_6X2_6]  48.52 10.59 180 top
U901  ADP5054ACPZ  [QFN48_7X7_PAD5_6X5_6]  88 13.17 270 bottom
U902  ADP125ARHZ-R7  [MSOP8_PAD2_16X1_73]  54.49 2.97 270 top
Y401  122.88MEGHZ  [YSML276W197H71]  116.62 61.26 270 bottom
Y402  122.88MEGHz  [YSML555W358H240]  116.62 61.26 270 bottom

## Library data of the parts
C6 C401-C405 C407-C409 C418-C425 C427-C444 C913 C915 C917 C919 C938 = CAP: User Part Number: UPN; Tolerance: 10; alternate symbols: (); part number: CAP_SM-0.1UF,16V,10,E007200,C0402; tolerance: 10
C101 C102 C136 C137 C609 C614 C617 C620 C627 C630 C643 C945 C948 = CAP: Tolerance: 10; User Part Number: UPN; alternate symbols: (C0402L_ALT); part number: CAP_SM-1UF,6.3V,10,E007449,C0402; tolerance: 10
C103-C135 C307 C308 C315 C316 C701 C704 C940 = CAP: Tolerance: 10; User Part Number: UPN; alternate symbols: (); part number: CAP_SM-0.1UF,6.3V,10,E011567,C0201; tolerance: 10
C201 C203 C204 C207 C208 C210 C211 C214 C215 C217 C218 C221 C222 C224 C225 C228 C301 C303 C312 C314 C320 C322 C338 C339 C341 C342 = CAP: User Part Number: UPN; alternate symbols: (); part number: CAP_SM-TBD0201,TBD0201,TBD0201,E005718,C0201
C240 C244 C246 C346 C348 = CAP: Tolerance: 5; User Part Number: UPN; alternate symbols: (); part number: CAP_SM-10PF,25V,5,E022849,C0201; tolerance: 5
C241 C243 C245 C247 C347 C349 = CAP: Tolerance: 5; User Part Number: UPN; alternate symbols: (); part number: CAP_SM-27PF,25V,5,E031190,C0201; tolerance: 5
C242 = CAP: Tolerance: 5; User Part Number: UPN; alternate symbols: (); part number: CAP_SM-82PF,25V,5,E025826,C0201; tolerance: 5
C248-C251 C336 C337 = CAP: Tolerance: 5; User Part Number: UPN; alternate symbols: (); part number: CAP_SM-18PF,50V,5,E028398,C0201; tolerance: 5
C304 C305 C410 C411 = CAP: Tolerance: 10; User Part Number: UPN; alternate symbols: (); part number: CAP_SM-100PF,25V,10,E006763,C0201; tolerance: 10
C323 C325 C327 C329 = CAP: User Part Number: UPN; alternate symbols: (C0201-2); part number: CAP_SM-TBD0201,TBD0201,TBD0201,E005718,C0201
C344 C350 = CAP: Tolerance: 2; User Part Number: UPN; alternate symbols: (); part number: CAP_SM-51PF,50V,2,E025910,C0201; tolerance: 2
C345 C351 = CAP: Tolerance: 5; User Part Number: UPN; alternate symbols: (); part number: CAP_SM-75PF,50V,5,E031191,C0201; tolerance: 5
C406 = CAP: User Part Number: UPN; Tolerance: 10; alternate symbols: (); part number: CAP_SM-0.33UF,10V,10,E011273,C0402; tolerance: 10
C412 C413 C914 C916 C918 C920 C935 C937 = CAP: User Part Number: UPN; Tolerance: 10; alternate symbols: (); part number: CAP_SM-0.01UF,25V,10,E010983,C0402; tolerance: 10
C414 = CAP: User Part Number: UPN; Tolerance: 5; alternate symbols: (); part number: CAP_SM-180PF,50V,5,E012612,C0402; tolerance: 5
C415 C426 C706 C902 C903 = CAP: User Part Number: UPN; Tolerance: 10; alternate symbols: (); part number: CAP_SM-1UF,6.3V,10,E007449,C0402; tolerance: 10
C416 = CAP: User Part Number: UPN; Tolerance: 5; alternate symbols: (C0402L_ALT); part number: CAP_SM-1000PF,50V,5,E012419,C0402; tolerance: 5
C417 = CAP: Tolerance: 20; User Part Number: UPN; alternate symbols: (); part number: CAP_SM-0.47UF,4V,20,E008196,C0201; tolerance: 20
C445 = CAP: User Part Number: UPN; alternate symbols: (C0402L_ALT); part number: CAP_SM-TBD0402,TBD0402,TBD0402,E000381,C0402
C601 C702 C703 C705 C936 C943 = CAP: Tolerance: 20; User Part Number: UPN; alternate symbols: (); part number: CAP_SM-10UF,6.3V,20,E007143,C0603; tolerance: 20
C602 C606 C607 C640 C641 = CAP: Tolerance: 20; User Part Number: UPN; alternate symbols: (); part number: CAP_SM-220UF,6.3V,20,E031200,C1210-2; tolerance: 20
C603 C610 C618 C621 C628 C637 = CAP: Tolerance: 20; User Part Number: UPN; alternate symbols: (C0603L); part number: CAP_SM-10UF,6.3V,20,E007143,C0603; tolerance: 20
C604 C608 C611 C615 C619 C622 C629 C632 C634 C636 C638 C642 C944 C947 = CAP: Tolerance: 10; User Part Number: UPN; alternate symbols: (C0201-2); part number: CAP_SM-0.1UF,6.3V,10,E011567,C0201; tolerance: 10
C605 C612 C623 C633 C635 C639 = CAP: User Part Number: UPN; Tolerance: 10; alternate symbols: (C0402L_ALT); part number: CAP_SM-1UF,6.3V,10,E007449,C0402; tolerance: 10
C613 C616 C631 = CAP: User Part Number: UPN; Tolerance: 20; alternate symbols: (C0603L); part number: CAP_SM-10UF,6.3V,20,E007143,C0603; tolerance: 20
C624-C626 = CAP: User Part Number: UPN; Tolerance: 20; alternate symbols: C1210H106; part number: CAP_SM-220UF,6.3V,20,E031200,C1210-2; tolerance: 20
C801-C804 C941 = CAP: Tolerance: 10; User Part Number: UPN; alternate symbols: (); part number: CAP_SM-0.01UF,10V,10,E007201,C0201; tolerance: 10
C901 C905 C907 C909 = CAP: Tolerance: 10; User Part Number: UPN; alternate symbols: (); part number: CAP_SM-10UF,25V,10,E014704,C0805H60; tolerance: 10
C904 C906 = CAP: User Part Number: UPN; Tolerance: 10; alternate symbols: (); part number: CAP_SM-0.0027UF,50V,10,E006649,C0402; tolerance: 10
C908 C910 = CAP: User Part Number: UPN; Tolerance: 10; alternate symbols: (); part number: CAP_SM-0.0033UF,50V,10,E007461,C0402; tolerance: 10
C911 C912 = CAP: User Part Number: UPN; alternate symbols: (); part number: CAP_SM-TBD0402,TBD0402,TBD0402,E000381,C0402
C921 C922 C924-C930 C932 C939 C949-C951 = CAP: Tolerance: 20; User Part Number: UPN; alternate symbols: (C0805L); part number: CAP_SM-47UF,6.3V,20,E008247,C0805H60; tolerance: 20
C931 = CAP: Tolerance: 20; User Part Number: UPN; alternate symbols: (); part number: CAP_SM-22UF,6.3V,20,E006534,C0805H53; tolerance: 20
C933 C934 = CAP: Tolerance: 10; User Part Number: UPN; alternate symbols: (); part number: CAP_SM-4.7UF,6.3V,10,E010382,C0603; tolerance: 10
C942 C946 = CAP: Tolerance: 20; User Part Number: UPN; alternate symbols: (); part number: CAP_SM-100UF,6.3V,20,E006532,C1210; tolerance: 20
CR901 = DIO: User Part Number: UPN; Tolerance: N/A; alternate symbols: (); part number: DIO_SM-S2A-LT,50V,N/A,E006935,DO214AA3; tolerance: N/A
DS401 DS402 DS902 = DIOLED: User Part Number: UPN; Tolerance: N/A; alternate symbols: (); part number: DIOLED_SM-LNJ326W83RA,2.5V,N/A,E027189,LED0603_A; tolerance: N/A
DS901 = DIOLED: Tolerance: N/A; User Part Number: UPN; alternate symbols: (); part number: DIOLED_SM-LNJ926W8CRA,N/A,N/A,E008232,LED0603; tolerance: N/A
E602 = FERRITE: Tolerance: 25; User Part Number: UPN; alternate symbols: (); part number: FERRITE_SM-1.8K OHM AT 100MEGHZ,25,E025769,L0402; tolerance: 25
E611 E905 = FERRITE: Tolerance: 25; User Part Number: UPN; alternate symbols: (); part number: FERRITE_SM-42OHM AT 100MEGHZ,25,E022207,L0805; tolerance: 25
E613 = FERRITE: Tolerance: 25; User Part Number: UPN; alternate symbols: (); part number: FERRITE_SM-1.8KOHM AT 100MEGHZ,25,E026780,L0402; tolerance: 25
E901 = FERRITE: Tolerance: 25; User Part Number: UPN; alternate symbols: (); part number: FERRITE_SM-120OHM,25,E012242,L0603; tolerance: 25
E902-E904 = FERRITE: Tolerance: 25; User Part Number: UPN; alternate symbols: (); part number: FERRITE_SM-470OHM,25,E021228,L0603; tolerance: 25
E906 E907 = FERRITE: Tolerance: 25; User Part Number: UPN; alternate symbols: (); part number: FERRITE_SM-30OHM,25,E015998,L0402; tolerance: 25
F901 F902 = FSFUSE: Tolerance: N/A; User Part Number: UPN; alternate symbols: (); part number: FSFUSE_SM-2A,63V,E005321,F1206; tolerance: N/A
J101 J305 J306 J402-J413 = CNBNC3P: Tolerance: N/A; User Part Number: UPN; alternate symbols: (); part number: CNBNC3P_SM-U.FL-R-SMT-1(01),E022198,CNHIROSE-U_FL-R-SMT-1; tolerance: N/A
J201-J204 J301 = CNBNC5P: Tolerance: N/A; User Part Number: UPN; alternate symbols: (CNAMPHENOL132255-11_ALT); part number: CNBNC5P_SM-132255-11,E017863,CNAMPHENOL132255-11; tolerance: N/A
J303 J304 = CNBNC5P: Tolerance: N/A; User Part Number: UPN; alternate symbols: (); part number: CNBNC5P_SM-132134-15,E026169,CNSMSMASQ276H379; tolerance: N/A
J401 = CNBNC5P: Tolerance: N/A; User Part Number: UPN; alternate symbols: (); part number: CNBNC5P_TH-142-0701-201,E000916,CNJOHNSON142-0701-201; tolerance: N/A
L307 L308 L315 L316 = IND: Tolerance: 5; User Part Number: UPN; alternate symbols: (L0603L); part number: IND_SM-43NH,5,E025961,L0603; tolerance: 5
L323 L325 L327 L329 L612 = IND: User Part Number: UPN; alternate symbols: (); part number: IND_SM-TBD0201,TBD0201,E007524,L0201
L401 = IND: User Part Number: UPN; alternate symbols: (L0402L); part number: IND_SM-TBD0402,TBD0402,E002418,L0402
L900 L901 = IND: User Part Number: UPN; Tolerance: 20; alternate symbols: (); part number: IND_SM-2.2UH,20,E016651,LSMSQ157H83; tolerance: 20
L902 L903 = IND: User Part Number: UPN; Tolerance: 20; alternate symbols: (); part number: IND_SM-6.8UH,20,E017909,LSMSQ157H122; tolerance: 20
P101 = CN20P: Tolerance: N/A; User Part Number: UPN; alternate symbols: (); part number: CN20P_TH-TSW-110-08-G-D,E000753,CNBERG2X10H330LD36; tolerance: N/A
P102 = CN16P_ODD_EVEN: Tolerance: N/A; User Part Number: UPN; alternate symbols: (); part number: CN16P_ODD_EVEN_TH-TSW-108-08-G-D,E007547,CNSAMTECTSW-108-08-G-D-ST; tolerance: N/A
P103 P104 = CN10P: User Part Number: UPN; Tolerance: N/A; alternate symbols: (); part number: CN10P_TH-TSW-105-08-G-D,E006587,CNSAMTEC2X5H338LD36; tolerance: N/A
P701 = CN20P_V2: Tolerance: N/A; User Part Number: UPN; alternate symbols: (); part number: CN20P_V2_SM-FTSH-110-01-L-DV-K,E020976,CNHDR2X10H251; tolerance: N/A
P801 = CN400P_A_K: User Part Number: UPN; Tolerance: N/A; alternate symbols: (); part number: CN400P_A_K_SM-ASP-134488-01,E011384,CNSAMTECASP-134488-01; tolerance: N/A
P901 = CN2P: User Part Number: UPN; Tolerance: N/A; alternate symbols: (); part number: CN2P_TH-Z5.530.3225.0,E008161,CNWIELAND3225; tolerance: N/A
P902 = CN3P: User Part Number: UPN; Tolerance: N/A; alternate symbols: (); part number: CN3P_TH-TSW-103-08-G-S,E000812,CNBERG1X3H205LD36; tolerance: N/A
P903-P907 = CN2P: User Part Number: UPN; Tolerance: N/A; alternate symbols: (); part number: CN2P_TH-TSW-102-08-G-S,E006296,CNSAMTEC1X2H330LD36; tolerance: N/A
Q901 = TRANNMOSFET_2PAD: Tolerance: N/A; User Part Number: UPN; alternate symbols: (); part number: TRANNMOSFET_2PAD_SM-SIA906EDJ-T1-GE3,E015819,POWERPAKSC70-6; tolerance: N/A
R101 = RES: Tolerance: 1; User Part Number: UPN; alternate symbols: (); part number: RES_SM-14.3K,E014068,1/20W,1,R0201; tolerance: 1
R102-R111 R113-R120 R832 R833 = RES: Tolerance: 1; User Part Number: UPN; alternate symbols: (); part number: RES_SM-10K,E004011,1/20W,1,R0201; tolerance: 1
R112 = RES: Tolerance: 1; User Part Number: UPN; alternate symbols: (); part number: RES_SM-1K,E004010,1/20W,1,R0201; tolerance: 1
R121 R405 R406 R418 R423 R426-R428 R431 R434 R450 = RES: Tolerance: 1; User Part Number: UPN; alternate symbols: (); part number: RES_SM-100,E007239,1/20W,1,R0201; tolerance: 1
R202 R205 R206 R209 R212 R213 R216 R219 R220 R223 R226 R227 R302 R304 R305 R307-R312 R453 R454 R612 R702 R704-R707 R801-R831 R834-R847 R912 = RES: Tolerance: 5; User Part Number: UPN; alternate symbols: (); part number: RES_SM-0,E004015,1/20W,5,R0201; tolerance: 5
R401 R412 = RES: User Part Number: UPN; Tolerance: 1; alternate symbols: (R0402L); part number: RES_SM-49.9,E003750,1/16W,1,R0402; tolerance: 1
R402 R407-R411 R413-R417 R419-R422 R424 R425 R429 R430 R432 R433 R435-R438 R444 R445 R448 R449 R451 R452 R601 R603-R611 R915 R921 R925 R929 R941 R942 = RES: User Part Number: UPN; Tolerance: 5; alternate symbols: (R0402L,R0402L_ALT); part number: RES_SM-0,E003438,N/A,5,R0402; tolerance: 5
R403 R404 = RES: User Part Number: UPN; Tolerance: 1; alternate symbols: (R0402L); part number: RES_SM-24.9,E003773,1/16W,1,R0402; tolerance: 1
R439 = RES: User Part Number: UPN; Tolerance: 1; alternate symbols: (R0402L); part number: RES_SM-10.2K,E019451,1/16W,1,R0402; tolerance: 1
R440-R443 R715-R727 R914 R920 R922 R924 R928 = RES: User Part Number: UPN; Tolerance: 1; alternate symbols: (R0402L,R0402L_ALT); part number: RES_SM-10K,E003751,1/10W,1,R0402; tolerance: 1
R446 R447 R935 = RES: User Part Number: UPN; Tolerance: 1; alternate symbols: (R0402L); part number: RES_SM-200,E003753,1/16W,1,R0402; tolerance: 1
R613 = RES: User Part Number: UPN; Tolerance: 1; alternate symbols: (R0402L); part number: RES_SM-0.1,E017078,1/6W,1,R0402; tolerance: 1
R701 = RES: Tolerance: 1; User Part Number: UPN; alternate symbols: (); part number: RES_SM-47K,E020665,1/20W,1,R0201; tolerance: 1
R708-R713 = RES: Tolerance: 1; User Part Number: UPN; alternate symbols: (); part number: RES_SM-20K,E004013,1/20W,1,R0201; tolerance: 1
R714 R909 = RES: User Part Number: UPN; Tolerance: 1; alternate symbols: (R0402L); part number: RES_SM-56K,E017978,1/10W,1,R0402; tolerance: 1
R848 = RES: User Part Number: UPN; Tolerance: 5; alternate symbols: (R0402L); part number: RES_SM-1K,E020936,1/16W,5,R0402; tolerance: 5
R901 = RES: Tolerance: 1; User Part Number: UPN; alternate symbols: (R0603L); part number: RES_SM-2K,E017866,1/16W,1,R0603; tolerance: 1
R902 = RES: Tolerance: 1; User Part Number: UPN; alternate symbols: (); part number: RES_SM-200,E004008,1/20W,1,R0201; tolerance: 1
R903 R906 = RES: User Part Number: UPN; Tolerance: 5; alternate symbols: (R0402L); part number: RES_SM-100K,E003464,1/10W,5,R0402; tolerance: 5
R904 R907 = RES: User Part Number: UPN; Tolerance: 1; alternate symbols: (R0402L); part number: RES_SM-10K,E003751,1/10W,1,R0402; tolerance: 1
R905 = RES: User Part Number: UPN; Tolerance: 1; alternate symbols: (R0402L); part number: RES_SM-43.2K,E018504,1/10W,1,R0402; tolerance: 1
R908 R911 R939 = RES: User Part Number: UPN; Tolerance: 1; alternate symbols: (R0402L); part number: RES_SM-20K,E003791,1/16W,1,R0402; tolerance: 1
R910 = RES: User Part Number: UPN; Tolerance: 1; alternate symbols: (R0402L); part number: RES_SM-14K,E019660,1/16W,1,R0402; tolerance: 1
R913 = RES: User Part Number: UPN; Tolerance: 1; alternate symbols: (R0402L); part number: RES_SM-22.1K,E007152,1/16W,1,R0402; tolerance: 1
R916 R923 = RES: User Part Number: UPN; Tolerance: 1; alternate symbols: (R0402L); part number: RES_SM-6.34K,E003777,1/16W,1,R0402; tolerance: 1
R917 = RES: User Part Number: UPN; Tolerance: 1; alternate symbols: (R0402L); part number: RES_SM-10.7K,E019637,1/16W,1,R0402; tolerance: 1
R918 R919 = RES: User Part Number: UPN; Tolerance: 1; alternate symbols: (R0402L,R0402L_ALT); part number: RES_SM-47K,E008189,1/16W,1,R0402; tolerance: 1
R926 = RES: User Part Number: UPN; Tolerance: 1; alternate symbols: (R0402L); part number: RES_SM-37.4K,E017173,1/10W,1,R0402; tolerance: 1
R927 = RES: User Part Number: UPN; Tolerance: 1; alternate symbols: (R0402L); part number: RES_SM-31.6K,E019881,1/10W,1,R0402; tolerance: 1
R930 = RES: User Part Number: UPN; Tolerance: 1; alternate symbols: (R0402L); part number: RES_SM-27.4K,E021819,1/10W,1,R0402; tolerance: 1
R931 = RES: User Part Number: UPN; Tolerance: 1; alternate symbols: (R0402L); part number: RES_SM-12.7K,E019976,1/10W,1,R0402; tolerance: 1
R932-R934 = RES: Tolerance: 1; User Part Number: UPN; alternate symbols: (R0603L); part number: RES_SM-0.1,E016658,1/10W,1,R0603; tolerance: 1
R936 R938 = RES: Tolerance: 5; User Part Number: UPN; alternate symbols: (R0603L); part number: RES_SM-0,E006826,1/10W,5,R0603; tolerance: 5
R937 = RES: Tolerance: 5; User Part Number: UPN; alternate symbols: (R0603L); part number: RES_SM-0.47,E015794,1/10W,5,R0603; tolerance: 5
R940 = RES: User Part Number: UPN; Tolerance: 1; alternate symbols: (R0402L); part number: RES_SM-4.99K,E006643,1/16W,1,R0402; tolerance: 1
T201 T202 T205 T207 T302 T303 = XFMRTCMXXXX_V5: Tolerance: N/A; User Part Number: UPN; alternate symbols: (); part number: XFMRTCMXXXX_V5_SM-TCM1-83X+,E018600,TSML150W160H160; tolerance: N/A
T301 = XFMRBD0826: User Part Number: UPN; Tolerance: N/A; alternate symbols: (); part number: XFMRBD0826_SM-HHM1595A1,E016462,T0805_A; tolerance: N/A
T401 = XFMRETC1: Tolerance: N/A; User Part Number: UPN; alternate symbols: (); part number: XFMRETC1_SM-MABA-007159-000000,E006308,ETC1; tolerance: N/A
TP400-TP403 TP601-TP614 TP701 TP702 TP801-TP819 TP901-TP904 = CNTP1P: Tolerance: N/A; User Part Number: UPN; alternate symbols: (); part number: CNTP1P_TH-WHT,E005683,CNKEY5001TP; tolerance: N/A
U101 = ADRV9009: User Part Number: UPN; Tolerance: N/A; alternate symbols: (); part number: ADRV9009_SM-ADRV9009,E029268,BGA196; tolerance: N/A
U102 = ICS25FL208K: Tolerance: N/A; User Part Number: UPN; alternate symbols: (); part number: ICS25FL208K_SM-S25FL208K0RMFI041,E019626,SO8; tolerance: N/A
U401 = AD9528: User Part Number: UPN; Tolerance: N/A; alternate symbols: (); part number: AD9528_SM-AD9528BCPZ,E019427,QFN72_10X10_PAD5_3X5_3; tolerance: N/A
U402 = CMOSNC7WV125K8X: Tolerance: N/A; User Part Number: UPN; alternate symbols: (); part number: CMOSNC7WV125K8X_SM-NC7WV125K8X,E017378,US8; tolerance: N/A
U403 = ADG3304: Tolerance: N/A; User Part Number: UPN; alternate symbols: (); part number: ADG3304_SM-ADG3304SRU-EP,E020776,TSSOP14; tolerance: N/A
U404 = ADG3301: Tolerance: N/A; User Part Number: UPN; alternate symbols: (); part number: ADG3301_SM-ADG3301BKSZ,E010847,SC70-6; tolerance: N/A
U405 = NC7WZ17P6X: Tolerance: N/A; User Part Number: UPN; alternate symbols: (); part number: NC7WZ17P6X_SM-NC7WZ16P6X,E002060,SC70; tolerance: N/A
U702 = ICM24CXX: Tolerance: N/A; User Part Number: UPN; alternate symbols: (); part number: ICM24CXX_SM-M24C02-FDW6TP,E031427,TSSOP8; tolerance: N/A
U703 = AD7291: User Part Number: UPN; Tolerance: N/A; alternate symbols: (); part number: AD7291_SM-AD7291BCPZ,E017361,QFN20_4X4_PAD2_6X2_6; tolerance: N/A
U901 = ADP5054: User Part Number: UPN; Tolerance: N/A; alternate symbols: (); part number: ADP5054_SM-ADP5054ACPZ,E019222,QFN48_7X7_PAD5_6X5_6; tolerance: N/A
U902 = ADP125: Tolerance: N/A; User Part Number: UPN; alternate symbols: (); part number: ADP125_SM-ADP125ARHZ-R7,E012587,MSOP8_PAD2_16X1_73; tolerance: N/A
Y401 = XTALOSC6P: Tolerance: N/A; User Part Number: UPN; alternate symbols: (); part number: XTALOSC6P_SM-122.88MEGHZ,E013348,YSML276W197H71; tolerance: N/A
Y402 = XTALOSC6P_V2: Tolerance: N/A; User Part Number: UPN; alternate symbols: (); part number: XTALOSC6P_V2_SM-122.88MEGHZ,E010834,YSML555W358H240; tolerance: N/A

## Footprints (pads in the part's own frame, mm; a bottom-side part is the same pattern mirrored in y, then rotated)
BGA196
  round 0.356 smd: A1(-5.2,-5.2) A2(-5.2,-4.4) A3(-5.2,-3.6) A4(-5.2,-2.8) A5(-5.2,-2) A6(-5.2,-1.2) A7(-5.2,-0.4) A8(-5.2,0.4) A9(-5.2,1.2) A10(-5.2,2) A11(-5.2,2.8) A12(-5.2,3.6) A13(-5.2,4.4) A14(-5.2,5.2) B1(-4.4,-5.2) B2(-4.4,-4.4) B3(-4.4,-3.6) B4(-4.4,-2.8) B5(-4.4,-2) B6(-4.4,-1.2) B7(-4.4,-0.4) B8(-4.4,0.4) B9(-4.4,1.2) B10(-4.4,2) B11(-4.4,2.8) B12(-4.4,3.6) B13(-4.4,4.4) B14(-4.4,5.2) C1(-3.6,-5.2) C2(-3.6,-4.4) C3(-3.6,-3.6) C4(-3.6,-2.8) C5(-3.6,-2) C6(-3.6,-1.2) C7(-3.6,-0.4) C8(-3.6,0.4) C9(-3.6,1.2) C10(-3.6,2) C11(-3.6,2.8) C12(-3.6,3.6) C13(-3.6,4.4) C14(-3.6,5.2) D1(-2.8,-5.2) D2(-2.8,-4.4) D3(-2.8,-3.6) D4(-2.8,-2.8) D5(-2.8,-2) D6(-2.8,-1.2) D7(-2.8,-0.4) D8(-2.8,0.4) D9(-2.8,1.2) D10(-2.8,2) D11(-2.8,2.8) D12(-2.8,3.6) D13(-2.8,4.4) D14(-2.8,5.2) E1(-2,-5.2) E2(-2,-4.4) E3(-2,-3.6) E4(-2,-2.8) E5(-2,-2) E6(-2,-1.2) E7(-2,-0.4) E8(-2,0.4) E9(-2,1.2) E10(-2,2) E11(-2,2.8) E12(-2,3.6) E13(-2,4.4) E14(-2,5.2) F1(-1.2,-5.2) F2(-1.2,-4.4) F3(-1.2,-3.6) F4(-1.2,-2.8) F5(-1.2,-2) F6(-1.2,-1.2) F7(-1.2,-0.4) F8(-1.2,0.4) F9(-1.2,1.2) F10(-1.2,2) F11(-1.2,2.8) F12(-1.2,3.6) F13(-1.2,4.4) F14(-1.2,5.2) G1(-0.4,-5.2) G2(-0.4,-4.4) G3(-0.4,-3.6) G4(-0.4,-2.8) G5(-0.4,-2) G6(-0.4,-1.2) G7(-0.4,-0.4) G8(-0.4,0.4) G9(-0.4,1.2) G10(-0.4,2) G11(-0.4,2.8) G12(-0.4,3.6) G13(-0.4,4.4) G14(-0.4,5.2) H1(0.4,-5.2) H2(0.4,-4.4) H3(0.4,-3.6) H4(0.4,-2.8) H5(0.4,-2) H6(0.4,-1.2) H7(0.4,-0.4) H8(0.4,0.4) H9(0.4,1.2) H10(0.4,2) H11(0.4,2.8) H12(0.4,3.6) H13(0.4,4.4) H14(0.4,5.2) J1(1.2,-5.2) J2(1.2,-4.4) J3(1.2,-3.6) J4(1.2,-2.8) J5(1.2,-2) J6(1.2,-1.2) J7(1.2,-0.4) J8(1.2,0.4) J9(1.2,1.2) J10(1.2,2) J11(1.2,2.8) J12(1.2,3.6) J13(1.2,4.4) J14(1.2,5.2) K1(2,-5.2) K2(2,-4.4) K3(2,-3.6) K4(2,-2.8) K5(2,-2) K6(2,-1.2) K7(2,-0.4) K8(2,0.4) K9(2,1.2) K10(2,2) K11(2,2.8) K12(2,3.6) K13(2,4.4) K14(2,5.2) L1(2.8,-5.2) L2(2.8,-4.4) L3(2.8,-3.6) L4(2.8,-2.8) L5(2.8,-2) L6(2.8,-1.2) L7(2.8,-0.4) L8(2.8,0.4) L9(2.8,1.2) L10(2.8,2) L11(2.8,2.8) L12(2.8,3.6) L13(2.8,4.4) L14(2.8,5.2) M1(3.6,-5.2) M2(3.6,-4.4) M3(3.6,-3.6) M4(3.6,-2.8) M5(3.6,-2) M6(3.6,-1.2) M7(3.6,-0.4) M8(3.6,0.4) M9(3.6,1.2) M10(3.6,2) M11(3.6,2.8) M12(3.6,3.6) M13(3.6,4.4) M14(3.6,5.2) N1(4.4,-5.2) N2(4.4,-4.4) N3(4.4,-3.6) N4(4.4,-2.8) N5(4.4,-2) N6(4.4,-1.2) N7(4.4,-0.4) N8(4.4,0.4) N9(4.4,1.2) N10(4.4,2) N11(4.4,2.8) N12(4.4,3.6) N13(4.4,4.4) N14(4.4,5.2) P1(5.2,-5.2) P2(5.2,-4.4) P3(5.2,-3.6) P4(5.2,-2.8) P5(5.2,-2) P6(5.2,-1.2) P7(5.2,-0.4) P8(5.2,0.4) P9(5.2,1.2) P10(5.2,2) P11(5.2,2.8) P12(5.2,3.6) P13(5.2,4.4) P14(5.2,5.2)
